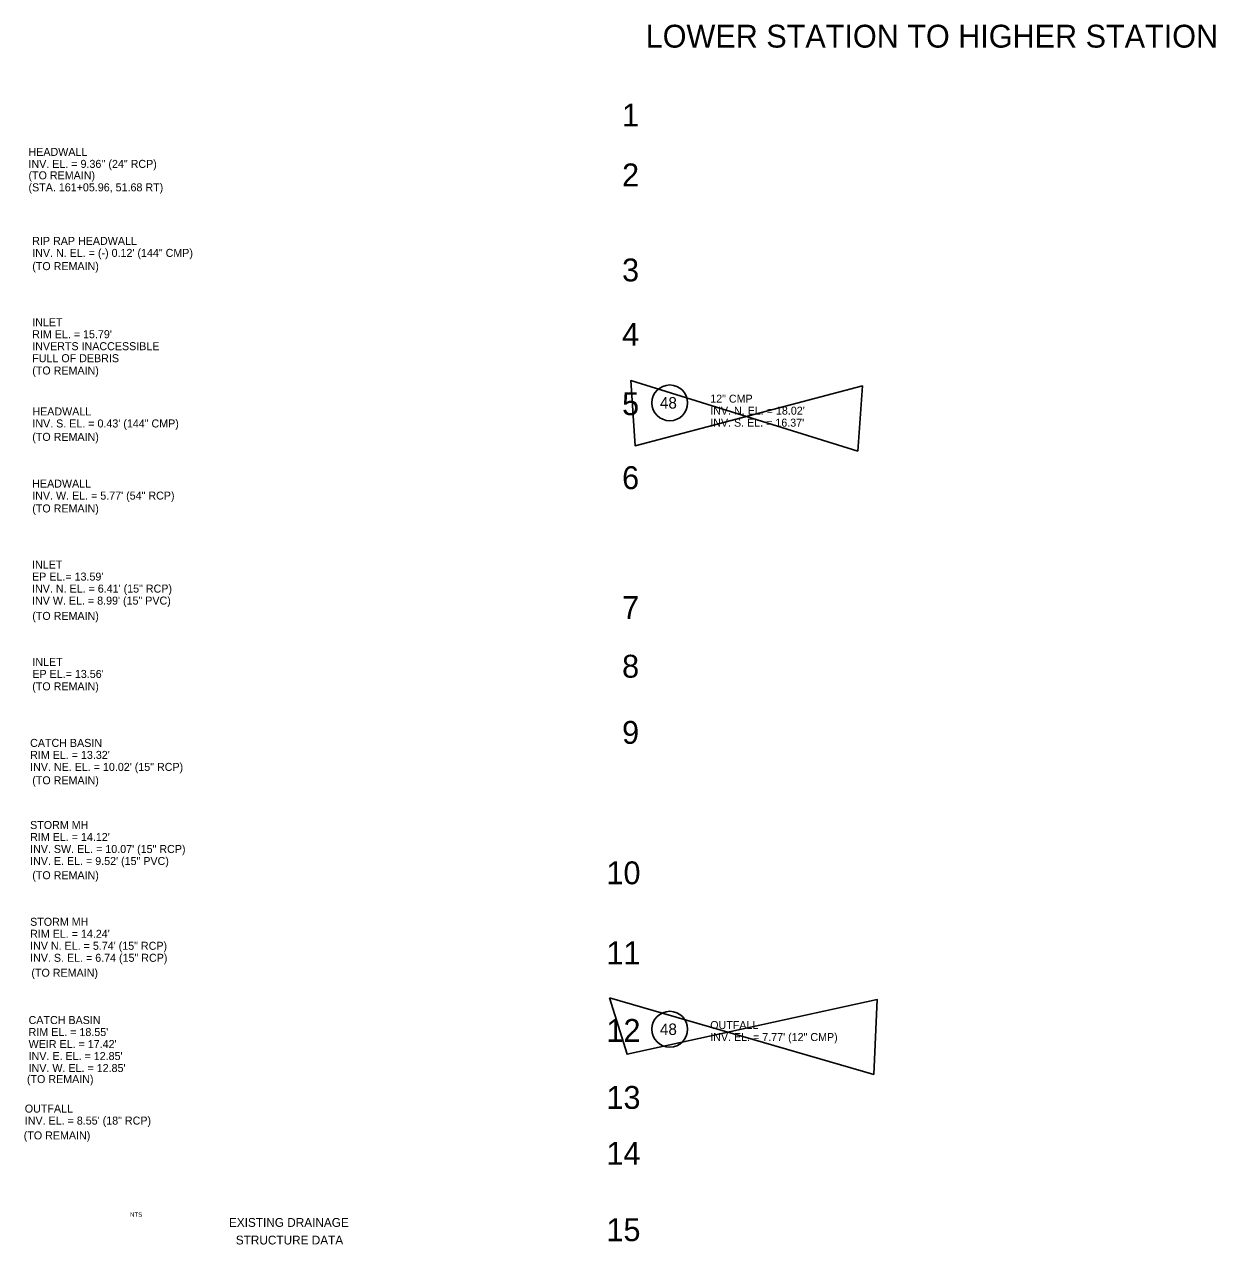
# Model space of a CAD drawing. Extents: x 28 to 1064, y -19 to 515.
# Drawn here: x 543 to 1064, y -19 to 515 of the extents above; entities that cross this region are included whole.
import ezdxf

# ---------------------------------------------------------------- set-up
doc = ezdxf.new("R2010")
doc.units = 0
for name, color, linetype in [('Default', 7, 'Continuous'), ('Miscellaneous6', 7, 'Continuous'), ('ScratchEle_dp', 7, 'Continuous'), ('TextLabel', 7, 'Continuous')]:
    doc.layers.add(name, color=color, linetype=linetype)

msp = doc.modelspace()

# ---------------------------------------------------------------- linework, layer by layer
at = {"layer": 'ScratchEle_dp'}
for points in [[(907.61, 328.22), (808.2, 359.06), (810.13, 330.53), (909.53, 356.75)], [(798.95, 89.04), (914.54, 55.49), (916.08, 88.26), (806.65, 64.36)]]:
    msp.add_lwpolyline(points, close=True, dxfattribs=at)
at = {"layer": 'TextLabel'}
for centre in [(825.29, 349.31), (825.29, 75.29)]:
    msp.add_circle(centre, 7.82, dxfattribs=at)

# ---------------------------------------------------------------- texts
at = {"layer": 'Default'}
for s, height, p in [('NTS', 1.927, (589.22, -6.78)), ('EXISTING DRAINAGE', 3.8546, (632.47, -11.18)), ('STRUCTURE DATA', 3.8546, (635.47, -18.88))]:
    msp.add_text(s, height=height, dxfattribs=at).set_placement(p)
at = {"layer": 'Miscellaneous6'}
for s, p in [('LOWER STATION TO HIGHER STATION', (814.76, 504.72)), ('1', (804.44, 470.25)), ('2', (804.44, 444.03)), ('3', (804.44, 402.44)), ('4', (804.44, 374.26)), ('5', (804.44, 343.94)), ('6', (804.44, 311.58)), ('7', (804.44, 254.74)), ('8', (804.44, 229.08)), ('9', (804.44, 200.14)), ('10', (797.61, 138.7)), ('11', (797.61, 103.67)), ('12', (797.61, 69.75)), ('13', (797.61, 40.45)), ('14', (797.61, 15.99)), ('15', (797.61, -17.44))]:
    msp.add_text(s, height=10, dxfattribs=at).set_placement(p)
at = {"layer": 'TextLabel'}
for s, p in [('HEADWALL', (544.79, 457.35)), ('INV. EL. = 9.36\'\' (24" RCP)', (544.79, 452.1)), ('(TO REMAIN)', (544.79, 447.1)), ('(STA. 161+05.96, 51.68 RT)', (544.79, 441.85)), ('RIP RAP HEADWALL', (546.42, 418.41)), ('INV. N. EL. = (-) 0.12\' (144" CMP)', (546.42, 413.16)), ('(TO REMAIN)', (546.44, 407.38)), ('INLET', (546.42, 382.84)), ("RIM EL. = 15.79'", (546.42, 377.59)), ('INVERTS INACCESSIBLE', (546.42, 372.34)), ('FULL OF DEBRIS', (546.42, 367.09)), ('(TO REMAIN)', (546.44, 361.71)), ('12" CMP', (842.99, 349.39)), ('HEADWALL', (546.48, 343.79)), ("INV. N. EL. = 18.02'", (842.99, 344.14)), ('INV. S. EL. = 0.43\' (144" CMP)', (546.48, 338.54)), ("INV. S. EL. = 16.37'", (842.99, 338.89)), ('(TO REMAIN)', (546.44, 332.68)), ('HEADWALL', (546.42, 312.23)), ('INV. W. EL. = 5.77\' (54" RCP)', (546.42, 306.98)), ('(TO REMAIN)', (546.44, 301.37)), ('INLET', (546.35, 276.8)), ("EP EL.= 13.59'", (546.35, 271.55)), ('INV. N. EL. = 6.41\' (15" RCP)', (546.35, 266.3)), ('INV W. EL. = 8.99\' (15" PVC)', (546.35, 261.05)), ('(TO REMAIN)', (546.44, 254.35)), ('INLET', (546.48, 234.21)), ("EP EL.= 13.56'", (546.48, 228.96)), ('(TO REMAIN)', (546.44, 223.55)), ('CATCH BASIN', (545.5, 198.79)), ("RIM EL. = 13.32'", (545.5, 193.54)), ('INV. NE. EL. = 10.02\' (15" RCP)', (545.5, 188.29)), ('(TO REMAIN)', (546.44, 182.44)), ('STORM MH', (545.5, 162.88)), ("RIM EL. = 14.12'", (545.5, 157.63)), ('INV. SW. EL. = 10.07\' (15" RCP)', (545.5, 152.38)), ('INV. E. EL. = 9.52\' (15" PVC)', (545.5, 147.13)), ('(TO REMAIN)', (546.44, 140.9)), ('STORM MH', (545.5, 120.53)), ("RIM EL. = 14.24'", (545.5, 115.28)), ('INV N. EL. = 5.74\' (15" RCP)', (545.5, 110.03)), ('INV. S. EL. = 6.74 (15" RCP)', (545.5, 104.78)), ('(TO REMAIN)', (546.06, 98.25)), ('CATCH BASIN ', (544.84, 77.55)), ("RIM EL. = 18.55'", (544.84, 72.3)), ('OUTFALL', (842.99, 75.36)), ("WEIR EL. = 17.42'", (544.84, 67.05)), ('INV. EL. = 7.77\' (12" CMP)', (842.99, 70.11)), ("INV. E. EL. = 12.85'", (544.84, 61.8)), ("INV. W. EL. = 12.85' ", (544.84, 56.55)), ('(TO REMAIN)', (544.11, 51.72)), ('OUTFALL', (543.17, 38.81)), ('INV. EL. = 8.55\' (18" RCP)', (543.17, 33.56)), ('(TO REMAIN)', (542.71, 27.08))]:
    msp.add_text(s, height=3.5, dxfattribs=at).set_placement(p)
for p in [(820.97, 346.81), (820.97, 72.78)]:
    msp.add_text('48', height=5, rotation=0.0168, dxfattribs=at).set_placement(p)

doc.saveas('drawing.dxf')
